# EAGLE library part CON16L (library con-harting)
CONNECTOR
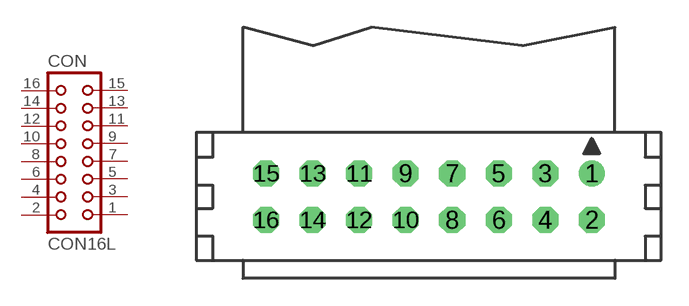
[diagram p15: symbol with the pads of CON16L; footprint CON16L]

Designator prefix CON

## CON16L (OC_FARNELL: unknown; OC_NEWARK: unknown)  [CON16L]
1  1  pas
2  2  pas
3  3  pas
4  4  pas
5  5  pas
6  6  pas
7  7  pas
8  8  pas
9  9  pas
10  10  pas
11  11  pas
12  12  pas
13  13  pas
14  14  pas
15  15  pas
16  16  pas

## Footprint CON16L (pad centres in mm)
CONNECTOR
drill 0.914 round: 1 8.89,1.27
drill 0.914 octagon: 2 8.89,-1.27; 3 6.35,1.27; 4 6.35,-1.27; 5 3.81,1.27; 6 3.81,-1.27; 7 1.27,1.27; 8 1.27,-1.27; 9 -1.27,1.27; 10 -1.27,-1.27; 11 -3.81,1.27; 12 -3.81,-1.27; 13 -6.35,1.27; 14 -6.35,-1.27; 15 -8.89,1.27; 16 -8.89,-1.27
